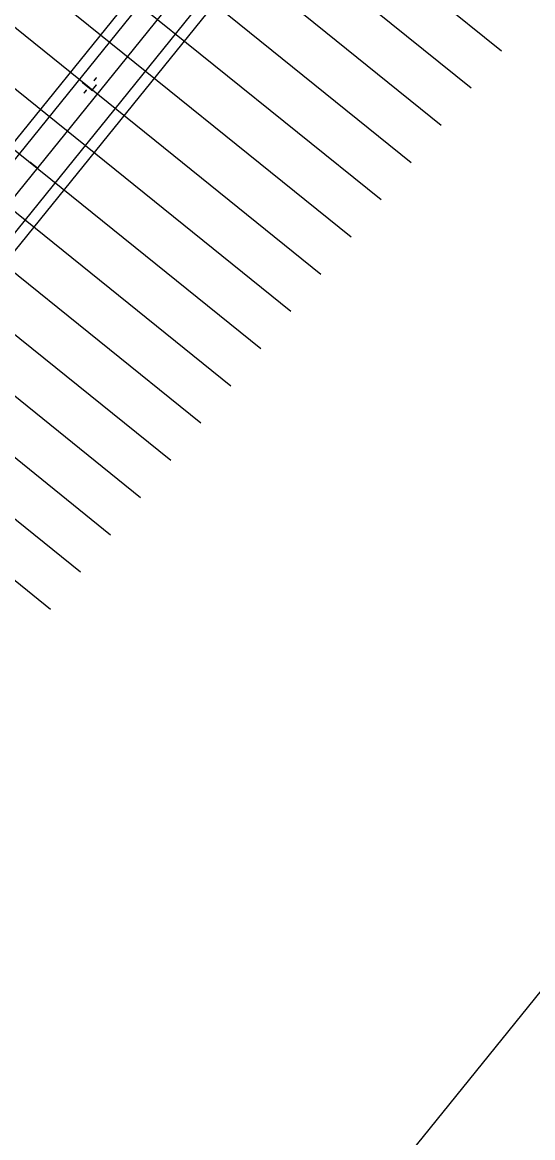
# Model space of a CAD drawing. Extents: x 2292992 to 2295123, y 892701 to 896230.
# Drawn here: x 2293840 to 2294107, y 892998 to 893581 of the extents above; entities that cross this region are included whole.
import ezdxf

# ---------------------------------------------------------------- set-up
doc = ezdxf.new("R2010")
doc.units = 0
for name, color, linetype in [('Prop EOT', 7, 'Continuous'), ('Prop Horizontal Alignment', 7, 'Continuous'), ('Prop Horizontal Alignment Tick Small', 7, 'Continuous'), ('Prop Roadway Bridge', 7, 'Continuous'), ('Scratch_Level_3', 7, 'Continuous'), ('Scratch_Level_4', 7, 'Continuous'), ('Sheet Layout Plan Border', 7, 'Continuous')]:
    doc.layers.add(name, color=color, linetype=linetype)

msp = doc.modelspace()

# ---------------------------------------------------------------- linework, layer by layer
at = {"layer": 'Prop EOT'}
for p, q in [((2293677.44, 893312.82), (2294149.49, 893897.76)), ((2293696.11, 893297.74), (2294168.17, 893882.69))]:
    msp.add_line(p, q, dxfattribs=at)
at = {"layer": 'Prop Horizontal Alignment'}
msp.add_line((2293686.78, 893305.28), (2294292.7, 894056.1), dxfattribs=at)
at = {"layer": 'Prop Horizontal Alignment Tick Small'}
msp.add_line((2293847.96, 893505.01), (2293844.07, 893508.15), dxfattribs=at)
at = {"layer": 'Prop Roadway Bridge'}
for p, q in [((2293801.93, 893476.63), (2293933.81, 893640.05)), ((2293829.94, 893454.02), (2293961.82, 893617.44))]:
    msp.add_line(p, q, dxfattribs=at)
at = {"layer": 'Scratch_Level_3'}
msp.add_line((2293686.78, 893305.28), (2294292.7, 894056.1), dxfattribs=at)
at = {"layer": 'Scratch_Level_4'}
for p, q in [((2293856.83, 893754.85), (2294090.29, 893566.45)), ((2293841.13, 893735.4), (2294074.59, 893546.99)), ((2293825.43, 893715.94), (2294058.89, 893527.54)), ((2293809.73, 893696.49), (2294043.19, 893508.08)), ((2293794.03, 893677.03), (2294027.49, 893488.63)), ((2293778.33, 893657.58), (2294011.79, 893469.17)), ((2293762.63, 893638.12), (2293996.09, 893449.72)), ((2293746.93, 893618.67), (2293980.39, 893430.26)), ((2293731.23, 893599.21), (2293964.69, 893410.81)), ((2293715.53, 893579.76), (2293948.99, 893391.35)), ((2293699.83, 893560.3), (2293933.29, 893371.9)), ((2293684.13, 893540.85), (2293917.59, 893352.44)), ((2293668.43, 893521.39), (2293901.89, 893332.99)), ((2293652.73, 893501.94), (2293886.19, 893313.53)), ((2293637.03, 893482.48), (2293870.49, 893294.08)), ((2293621.33, 893463.03), (2293854.79, 893274.62))]:
    msp.add_line(p, q, dxfattribs=at)
at = {"layer": 'Sheet Layout Plan Border'}
msp.add_lwpolyline([(2293808.88, 892701.06), (2294688.51, 893790.22), (2293871.64, 894449.94), (2292992.02, 893360.79)], close=True, dxfattribs=at)

# ---------------------------------------------------------------- texts
at = {"layer": 'Prop Horizontal Alignment'}
msp.add_text('-L-', height=7, rotation=51.09608, dxfattribs=at).set_placement((2293874.11, 893542.21))

doc.saveas('drawing.dxf')
